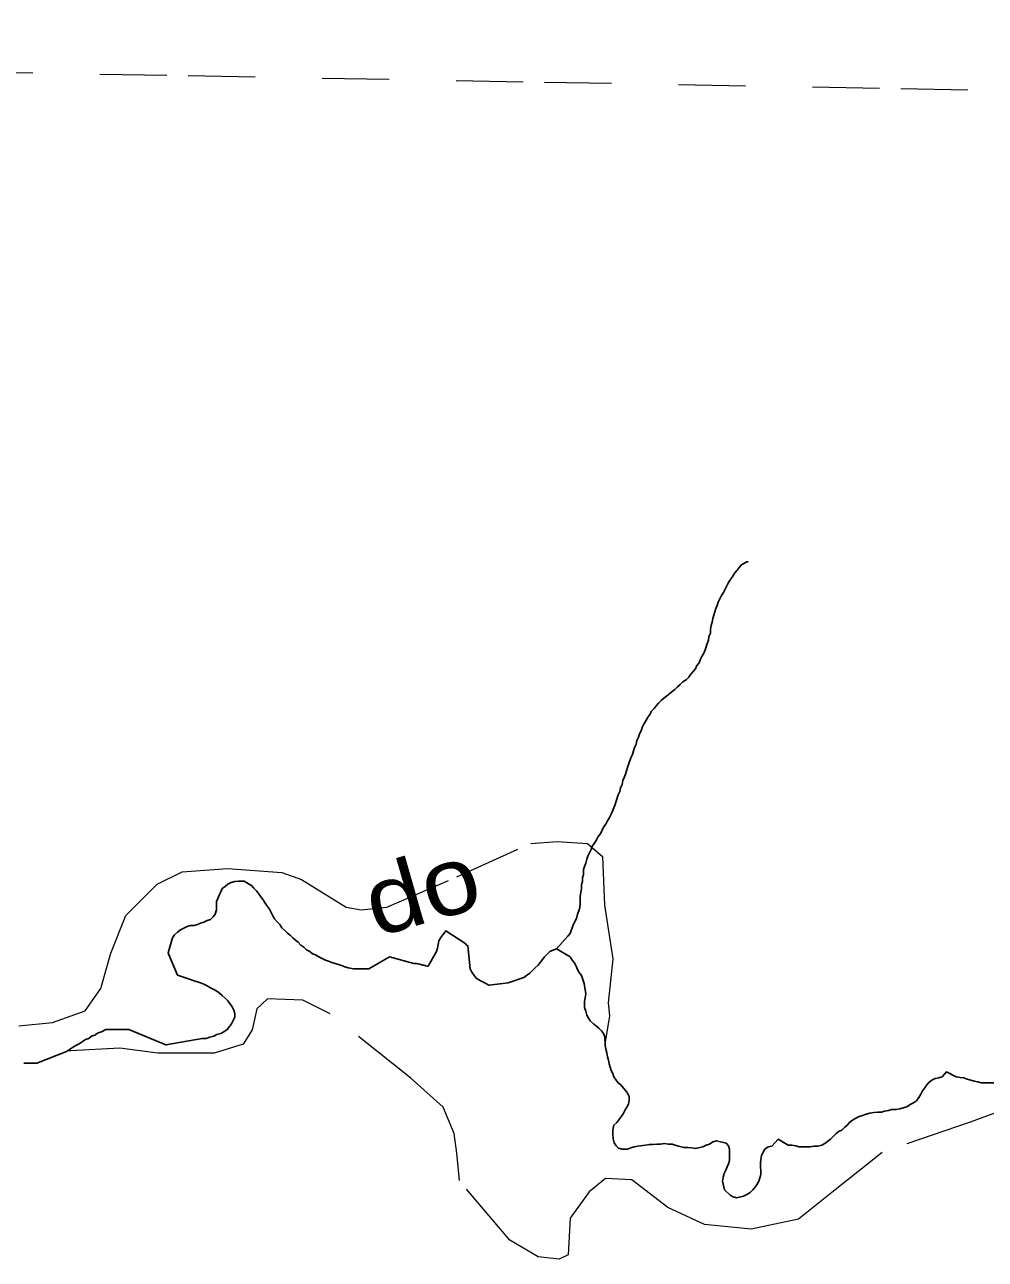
# Model space of a CAD drawing. Extents: x 785.9 to 812.4, y 7674.9 to 7703.1.
# Drawn here: x 802.609 to 804.042, y 7701.001 to 7702.842 of the extents above; entities that cross this region are included whole.
import ezdxf
from ezdxf.enums import TextEntityAlignment as Align

# ---------------------------------------------------------------- set-up
doc = ezdxf.new("R2010")
doc.units = 0
doc.header["$LTSCALE"] = 0.04
doc.linetypes.add('SHORT_DASHED', pattern=[2.7, 1.5, -1.2])
for name, color, linetype, lineweight in [('21', 7, 'SHORT_DASHED', 13), ('53', 7, 'SHORT_DASHED', 13), ('7', 7, 'Continuous', 25)]:
    doc.layers.add(name, color=color, linetype=linetype, lineweight=lineweight)
doc.layers.add('61', color=7, linetype='Continuous')

msp = doc.modelspace()

# ---------------------------------------------------------------- linework, layer by layer
at = {"layer": '21'}
for points in [[(802.6005, 7701.3492), (802.6504, 7701.3541), (802.6993, 7701.3717), (802.7228, 7701.405), (802.7374, 7701.4578), (802.7599, 7701.5136), (802.8069, 7701.5605), (802.844, 7701.5791), (802.9115, 7701.584), (802.9927, 7701.5781), (803.022, 7701.5674), (803.0885, 7701.5263), (803.111, 7701.5224), (803.1492, 7701.5263), (803.2538, 7701.5713), (803.3643, 7701.6212), (803.4034, 7701.6241), (803.4484, 7701.6212), (803.4709, 7701.6016), (803.4739, 7701.5293), (803.4866, 7701.449), (803.4797, 7701.3835), (803.4817, 7701.3639), (803.4749, 7701.3246)], [(804.0859, 7701.2299), (804.0194, 7701.2055), (803.8884, 7701.1605), (803.818, 7701.1047), (803.7632, 7701.0607), (803.6928, 7701.046), (803.6234, 7701.0528), (803.5686, 7701.0783), (803.5148, 7701.1194), (803.4757, 7701.1213), (803.4512, 7701.1018), (803.4229, 7701.0626), (803.4199, 7701.0078), (803.4063, 7701.001), (803.375, 7701.0049), (803.3329, 7701.0294), (803.2576, 7701.1184), (803.2537, 7701.1595), (803.2498, 7701.1888), (803.2332, 7701.228), (803.1853, 7701.271), (803.065, 7701.3669), (803.0239, 7701.3874), (802.9711, 7701.3894), (802.9555, 7701.3747), (802.9486, 7701.3434), (802.9349, 7701.3219), (802.8919, 7701.3082), (802.8078, 7701.3082), (802.7511, 7701.316), (802.6777, 7701.3121), (802.6729, 7701.3119)]]:
    msp.add_lwpolyline(points, dxfattribs=at)
at = {"layer": '53'}
msp.add_lwpolyline([(798.5996, 7702.8423), (799.1312, 7702.8329), (799.6629, 7702.8234), (800.1945, 7702.8139), (800.7262, 7702.8044), (801.2578, 7702.7949), (801.7895, 7702.7854), (802.3212, 7702.7759), (802.8528, 7702.7663), (803.3845, 7702.7567), (803.9162, 7702.7471), (804.4478, 7702.7375), (804.9795, 7702.7279), (805.5112, 7702.7182)], dxfattribs=at)
at = {"layer": '7'}
for points in [[(803.6884, 7702.041), (803.6864, 7702.041), (803.6783, 7702.0369), (803.675, 7702.0329), (803.6718, 7702.0288), (803.6686, 7702.0248), (803.6653, 7702.0199), (803.6621, 7702.0151), (803.6588, 7702.0102), (803.6564, 7702.0054), (803.654, 7702.0005), (803.6516, 7701.9957)], [(803.6516, 7701.9957), (803.6483, 7701.9908), (803.6459, 7701.986), (803.6435, 7701.9811), (803.6419, 7701.9762), (803.6402, 7701.9714), (803.6386, 7701.9665), (803.637, 7701.9617), (803.6354, 7701.9568), (803.6346, 7701.9512), (803.633, 7701.9463), (803.6321, 7701.9406), (803.6321, 7701.935), (803.6297, 7701.9301), (803.6289, 7701.9245), (803.6273, 7701.9196), (803.624, 7701.9099), (803.6224, 7701.905), (803.6192, 7701.9002), (803.6168, 7701.8953), (803.6151, 7701.8905), (803.6119, 7701.8864), (803.6095, 7701.8816), (803.6062, 7701.8775), (803.603, 7701.8735), (803.5998, 7701.8694), (803.5957, 7701.8654), (803.5909, 7701.8622), (803.5868, 7701.8581), (803.5828, 7701.8549), (803.5787, 7701.8508), (803.5747, 7701.8476), (803.5666, 7701.8411), (803.5626, 7701.8379), (803.5585, 7701.8346), (803.5545, 7701.8306), (803.5512, 7701.8266), (803.548, 7701.8225), (803.5439, 7701.8185), (803.5415, 7701.8136), (803.5383, 7701.8088), (803.5359, 7701.8039), (803.5326, 7701.799), (803.5302, 7701.7942), (803.5286, 7701.7893), (803.5261, 7701.7845), (803.5245, 7701.7796), (803.5221, 7701.7748), (803.5213, 7701.7691), (803.5189, 7701.7642), (803.5172, 7701.7594), (803.5156, 7701.7537), (803.5132, 7701.7489), (803.51, 7701.7392), (803.5083, 7701.7343), (803.5051, 7701.7246), (803.5035, 7701.7197), (803.5011, 7701.7149), (803.5003, 7701.7092), (803.4978, 7701.7044), (803.497, 7701.6987), (803.4946, 7701.6939), (803.4914, 7701.6841), (803.4897, 7701.6793), (803.4881, 7701.6744), (803.4857, 7701.6696), (803.4841, 7701.6647), (803.4816, 7701.6599), (803.4784, 7701.655), (803.476, 7701.6502), (803.4727, 7701.6453), (803.4679, 7701.6356), (803.4646, 7701.6315), (803.4622, 7701.6267), (803.459, 7701.6218), (803.4557, 7701.617), (803.4541, 7701.6121), (803.4517, 7701.6073), (803.4493, 7701.6024), (803.4477, 7701.5976), (803.446, 7701.5919), (803.4444, 7701.587), (803.4428, 7701.5822), (803.4428, 7701.5749), (803.4412, 7701.5701), (803.4412, 7701.5644), (803.4396, 7701.5595), (803.4396, 7701.5539), (803.4388, 7701.5482), (803.4379, 7701.5425), (803.4379, 7701.5312), (803.4371, 7701.5256), (803.4355, 7701.5207), (803.4339, 7701.5158), (803.4323, 7701.5094), (803.4274, 7701.4997), (803.4226, 7701.4867), (803.4193, 7701.4827), (803.4023, 7701.4641)], [(802.7, 7701.3289), (802.7049, 7701.3305), (802.7089, 7701.3338), (802.7138, 7701.3354), (802.7186, 7701.3386), (802.7235, 7701.3403), (802.7299, 7701.3435), (802.7308, 7701.3435), (802.7324, 7701.3435), (802.734, 7701.3435), (802.7356, 7701.3435), (802.7372, 7701.3435), (802.7388, 7701.3435), (802.7405, 7701.3435), (802.7421, 7701.3435), (802.7437, 7701.3435), (802.7453, 7701.3435), (802.7469, 7701.3435), (802.7486, 7701.3435), (802.7502, 7701.3435), (802.7518, 7701.3435), (802.7534, 7701.3435), (802.755, 7701.3435), (802.7566, 7701.3435), (802.7583, 7701.3435), (802.7599, 7701.3435), (802.7615, 7701.3435), (802.7631, 7701.3435), (802.7647, 7701.3435), (802.8198, 7701.3208), (802.8198, 7701.3208), (802.874, 7701.3305), (802.8796, 7701.3305), (802.8853, 7701.3322), (802.891, 7701.3338), (802.8958, 7701.3362), (802.9015, 7701.3378), (802.9063, 7701.3403), (802.9112, 7701.3435), (802.9144, 7701.3483), (802.9177, 7701.3524), (802.9201, 7701.3573), (802.9225, 7701.3621), (802.9225, 7701.3678), (802.9209, 7701.3726), (802.9185, 7701.3775), (802.9152, 7701.3823), (802.912, 7701.3864), (802.908, 7701.3904), (802.9039, 7701.3945), (802.8999, 7701.3977), (802.8958, 7701.4009), (802.891, 7701.4034), (802.8861, 7701.4058), (802.8813, 7701.409), (802.8764, 7701.4115), (802.8715, 7701.4131), (802.8618, 7701.4163), (802.8521, 7701.4196), (802.8506, 7701.4201), (802.8491, 7701.4206), (802.8475, 7701.4211), (802.846, 7701.4216), (802.8445, 7701.4221), (802.8429, 7701.4226), (802.8414, 7701.4231), (802.8398, 7701.4236), (802.8383, 7701.4242), (802.8368, 7701.4247), (802.8238, 7701.4568), (802.8238, 7701.4568), (802.8232, 7701.4583), (802.8295, 7701.4802), (802.8327, 7701.4851), (802.8368, 7701.4891), (802.8416, 7701.4924), (802.8465, 7701.4948), (802.8513, 7701.4972), (802.8562, 7701.4989), (802.8618, 7701.4989), (802.8667, 7701.5005), (802.8715, 7701.5021), (802.8764, 7701.5037), (802.8813, 7701.5061), (802.8861, 7701.5078), (802.8902, 7701.5118), (802.8934, 7701.5158), (802.895, 7701.5223), (802.895, 7701.5288), (802.895, 7701.5345), (802.8974, 7701.5393), (802.8991, 7701.5442), (802.9015, 7701.549), (802.9039, 7701.5539), (802.908, 7701.5571), (802.912, 7701.5603), (802.9169, 7701.5628), (802.9225, 7701.5644), (802.9282, 7701.5652), (802.9363, 7701.5652), (802.9428, 7701.5612)], [(802.9428, 7701.5612), (802.9476, 7701.5587), (802.9508, 7701.5547), (802.9549, 7701.5506), (802.9581, 7701.5466), (802.9614, 7701.5417), (802.9646, 7701.5369), (802.9678, 7701.532), (802.9711, 7701.5272), (802.9743, 7701.5231), (802.9767, 7701.5183), (802.9792, 7701.5134), (802.9816, 7701.5086), (802.9856, 7701.5045), (802.9897, 7701.5005), (802.9929, 7701.4956), (802.997, 7701.4916), (803.001, 7701.4875), (803.0051, 7701.4843), (803.0091, 7701.4802), (803.0131, 7701.477), (803.0172, 7701.4738), (803.0212, 7701.4697), (803.0253, 7701.4665), (803.0293, 7701.4624), (803.0342, 7701.46), (803.0382, 7701.4568), (803.0431, 7701.4552), (803.0479, 7701.4519), (803.0528, 7701.4495), (803.0576, 7701.4471), (803.0625, 7701.4454), (803.0674, 7701.4438), (803.0722, 7701.4422), (803.0771, 7701.4406), (803.0819, 7701.439), (803.0868, 7701.4374), (803.0916, 7701.4357), (803.0997, 7701.4341), (803.1054, 7701.4341), (803.1062, 7701.4341), (803.1078, 7701.4341), (803.1094, 7701.4341), (803.1111, 7701.4341), (803.1127, 7701.4341), (803.1143, 7701.4341), (803.1159, 7701.4341), (803.1175, 7701.4341), (803.1191, 7701.4341), (803.1208, 7701.4341), (803.1224, 7701.4341), (803.1531, 7701.4519), (803.1531, 7701.4519), (803.1895, 7701.4422), (803.1936, 7701.4422), (803.1952, 7701.4418), (803.1967, 7701.4415), (803.1983, 7701.4411), (803.1999, 7701.4407), (803.2015, 7701.4403), (803.203, 7701.4399), (803.2046, 7701.4396), (803.2062, 7701.4392), (803.2077, 7701.4388), (803.2093, 7701.4384), (803.2109, 7701.4381), (803.2235, 7701.46), (803.2251, 7701.4649), (803.226, 7701.4705), (803.2268, 7701.4762), (803.23, 7701.481), (803.2324, 7701.4843), (803.2334, 7701.4856), (803.2344, 7701.4869), (803.2353, 7701.4882), (803.2363, 7701.4895), (803.2373, 7701.4908), (803.2672, 7701.4713), (803.2672, 7701.4705), (803.2686, 7701.4696), (803.2699, 7701.4687), (803.2737, 7701.4341), (803.2761, 7701.4293), (803.2794, 7701.4244), (803.2826, 7701.4204), (803.2874, 7701.4171), (803.2891, 7701.4163), (803.2905, 7701.4156), (803.292, 7701.4149), (803.2934, 7701.4141), (803.2949, 7701.4134), (803.2963, 7701.4127), (803.2977, 7701.412), (803.2992, 7701.4113), (803.3006, 7701.4105), (803.3021, 7701.4098), (803.3303, 7701.4131), (803.3303, 7701.4131), (803.3538, 7701.4212), (803.3578, 7701.4244), (803.3627, 7701.4276)], [(803.3627, 7701.4276), (803.3667, 7701.4317), (803.3708, 7701.4357), (803.3748, 7701.4398), (803.3781, 7701.4438), (803.3813, 7701.4479), (803.3845, 7701.4519), (803.3886, 7701.456), (803.3926, 7701.46), (803.3959, 7701.4616), (803.4023, 7701.4641)], [(803.4023, 7701.4641), (803.4226, 7701.4519), (803.4258, 7701.4471), (803.429, 7701.443), (803.4315, 7701.4382), (803.4339, 7701.4333), (803.4363, 7701.4285), (803.4396, 7701.4244), (803.4436, 7701.4123), (803.446, 7701.3969), (803.4452, 7701.3912), (803.4444, 7701.3856), (803.4444, 7701.3767), (803.446, 7701.371), (803.4477, 7701.3653), (803.4501, 7701.3605), (803.4533, 7701.3564), (803.4574, 7701.3524), (803.4655, 7701.3459), (803.4695, 7701.3419), (803.4727, 7701.3378), (803.4744, 7701.333), (803.4752, 7701.32), (803.476, 7701.3144), (803.4776, 7701.3087), (803.4784, 7701.303), (803.48, 7701.2982), (803.4808, 7701.2925), (803.4824, 7701.2877), (803.4841, 7701.2828), (803.4865, 7701.278), (803.4881, 7701.2731), (803.4914, 7701.2682), (803.4946, 7701.2642), (803.4986, 7701.261), (803.5051, 7701.2529), (803.5083, 7701.2488), (803.5108, 7701.244), (803.5108, 7701.2383), (803.51, 7701.2326)], [(802.6078, 7701.2933), (802.6094, 7701.2933), (802.611, 7701.2933), (802.6126, 7701.2933), (802.6142, 7701.2933), (802.6159, 7701.2933), (802.6175, 7701.2933), (802.6191, 7701.2933), (802.6207, 7701.2933), (802.6223, 7701.2933), (802.6239, 7701.2933), (802.6256, 7701.2933), (802.6272, 7701.2933), (802.6717, 7701.3111), (802.6806, 7701.3168), (802.6854, 7701.32), (802.6903, 7701.3225), (802.6952, 7701.3257), (802.7, 7701.3289)], [(803.6038, 7701.1671), (803.6095, 7701.1663), (803.6208, 7701.1687), (803.6257, 7701.1711), (803.6305, 7701.1728), (803.6354, 7701.176), (803.641, 7701.1776), (803.6556, 7701.1744), (803.6588, 7701.1703), (803.6605, 7701.1655), (803.6605, 7701.1485), (803.6588, 7701.1436), (803.6572, 7701.1388), (803.6548, 7701.1339), (803.6524, 7701.1291), (803.6508, 7701.1234), (803.6499, 7701.1177), (803.6532, 7701.1048), (803.6613, 7701.0967), (803.6661, 7701.0943), (803.671, 7701.0927), (803.6815, 7701.0951), (803.6864, 7701.0975), (803.6912, 7701.1008), (803.6953, 7701.1048), (803.6985, 7701.1088), (803.7017, 7701.1129), (803.7042, 7701.1177), (803.7058, 7701.1226), (803.7074, 7701.1275), (803.7074, 7701.1331), (803.7066, 7701.1388), (803.7066, 7701.1444), (803.7074, 7701.1501), (803.7082, 7701.1558), (803.7106, 7701.1606), (803.7131, 7701.1655), (803.7179, 7701.1687), (803.7236, 7701.1695), (803.7333, 7701.18), (803.7478, 7701.1711), (803.7535, 7701.1711), (803.7592, 7701.1703), (803.764, 7701.1687), (803.781, 7701.1687), (803.7867, 7701.1695), (803.7924, 7701.1695), (803.798, 7701.1711), (803.8029, 7701.1736), (803.811, 7701.18), (803.815, 7701.1841), (803.8191, 7701.1881), (803.8231, 7701.1914), (803.828, 7701.1938), (803.832, 7701.1978), (803.836, 7701.2011), (803.8393, 7701.2051), (803.8441, 7701.2084), (803.849, 7701.2116), (803.8538, 7701.214), (803.8587, 7701.2157), (803.8644, 7701.2173), (803.87, 7701.2189), (803.8757, 7701.2197), (803.8814, 7701.2205), (803.887, 7701.2205), (803.8919, 7701.2221), (803.8975, 7701.2229), (803.9024, 7701.2246), (803.9089, 7701.2246), (803.9145, 7701.2254), (803.9194, 7701.227), (803.9251, 7701.2286), (803.9299, 7701.2318), (803.9348, 7701.2343), (803.9396, 7701.2375), (803.9429, 7701.2424), (803.9461, 7701.2472), (803.9485, 7701.2521), (803.9518, 7701.2569), (803.955, 7701.261), (803.9582, 7701.265), (803.9623, 7701.2682), (803.9671, 7701.2707), (803.9728, 7701.2715), (803.9776, 7701.2731), (803.9841, 7701.2804), (803.9987, 7701.2731), (804.0043, 7701.2723), (804.01, 7701.2715), (804.0149, 7701.2699), (804.0205, 7701.2682), (804.0254, 7701.2666), (804.031, 7701.2658), (804.0359, 7701.2642), (804.0586, 7701.2642)], [(803.51, 7701.2326), (803.5075, 7701.2278), (803.5043, 7701.2229), (803.5019, 7701.2181), (803.4986, 7701.2132), (803.4954, 7701.2092), (803.4922, 7701.2051), (803.4881, 7701.2011), (803.487, 7701.1966), (803.4866, 7701.1938), (803.4864, 7701.1877), (803.4868, 7701.1806), (803.4886, 7701.1749), (803.4916, 7701.17), (803.4948, 7701.1666), (803.5005, 7701.1653), (803.5083, 7701.1655), (803.5132, 7701.1671), (803.5181, 7701.1687), (803.5237, 7701.1695), (803.535, 7701.1711), (803.5407, 7701.172), (803.5464, 7701.172), (803.552, 7701.1728), (803.5577, 7701.1728), (803.5634, 7701.1736), (803.569, 7701.1728), (803.5747, 7701.1728), (803.5795, 7701.1711), (803.5844, 7701.1695), (803.5925, 7701.1679), (803.5982, 7701.1679), (803.6038, 7701.1671)]]:
    msp.add_lwpolyline(points, dxfattribs=at)

# ---------------------------------------------------------------- texts
at = {"layer": '61', "width": 1.15}
msp.add_text('do', height=0.1, rotation=15.989, dxfattribs=at).set_placement((803.2151, 7701.5047), align=Align.CENTER)

doc.saveas('drawing.dxf')
